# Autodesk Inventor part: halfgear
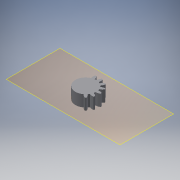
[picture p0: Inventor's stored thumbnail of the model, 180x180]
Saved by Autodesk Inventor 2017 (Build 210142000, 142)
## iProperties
Created: 2017-05
Part Number: halfgear
Material: Generic
Document SubType Name: Modeling
Designer: 1717440
Density: 1 g/cm^3
Appearance: Default
Author: 1717440
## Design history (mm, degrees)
workplane "Work Plane1"
sketch "Sketch1"
  geometry: L1 (-62.321, -3.687)-(-62.321, 3.767) reference; L2 (-22.321, -8.598)-(2.723, -8.598) reference; L3 (2.723, 8.678)-(-22.321, 8.678) reference; L4 (-0.521, 6.54)-(2.723, 6.54) reference; L5 (2.723, -6.46)-(1.723, -4.728) reference; L6 (1.723, -4.728)-(1.123, -4.728) reference; L7 (1.123, -4.728)-(0.123, -6.46) reference; L8 (0.123, -6.46)-(-0.477, -6.46) reference; L9 (-0.977, -5.594)-(-0.477, -6.46) reference; L10 (-2.577, -5.594)-(-0.977, -5.594) reference; L11 (-3.077, -6.46)-(-2.577, -5.594) reference; L12 (-3.077, -6.46)-(-3.677, -6.46) reference; L13 (-4.677, -4.728)-(-3.677, -6.46) reference; L14 (-5.277, -4.728)-(-4.677, -4.728) reference; L15 (-6.277, -6.46)-(-5.277, -4.728) reference; L16 (-6.277, -6.46)-(-6.877, -6.46) reference; L17 (-7.877, -4.728)-(-6.877, -6.46) reference; L18 (-8.477, -4.728)-(-7.877, -4.728) reference; L19 (-9.477, -6.46)-(-8.477, -4.728) reference; L20 (-9.477, -6.46)-(-10.077, -6.46) reference; L21 (-11.077, -4.728)-(-10.077, -6.46) reference; L22 (-11.677, -4.728)-(-11.077, -4.728) reference; L23 (-12.677, -6.46)-(-11.677, -4.728) reference; L24 (-12.677, -6.46)-(-13.277, -6.46) reference; L25 (-14.277, -4.728)-(-13.277, -6.46) reference; L26 (-14.877, -4.728)-(-14.277, -4.728) reference; L27 (-15.877, -6.46)-(-14.877, -4.728) reference; L28 (-15.877, -6.46)-(-16.477, -6.46) reference; L29 (-16.977, -5.594)-(-16.477, -6.46) reference; L30 (-18.577, -5.594)-(-16.977, -5.594) reference; L31 (-19.077, -6.46)-(-18.577, -5.594) reference; L32 (-19.077, -6.46)-(-22.321, -6.46) reference; L33 (-21.321, 4.808)-(-22.321, 6.54) reference; L34 (-20.721, 4.808)-(-21.321, 4.808) reference; L35 (-19.721, 6.54)-(-20.721, 4.808) reference; L36 (-19.721, 6.54)-(-19.121, 6.54) reference; L37 (-18.621, 5.674)-(-19.121, 6.54) reference; L38 (-17.021, 5.674)-(-18.621, 5.674) reference; L39 (-16.521, 6.54)-(-17.021, 5.674) reference; L40 (-16.521, 6.54)-(-15.921, 6.54) reference; L41 (-14.921, 4.808)-(-15.921, 6.54) reference; L42 (-14.321, 4.808)-(-14.921, 4.808) reference; L43 (-13.321, 6.54)-(-14.321, 4.808) reference; L44 (-13.321, 6.54)-(-12.721, 6.54) reference; L45 (-11.721, 4.808)-(-12.721, 6.54) reference; L46 (-11.121, 4.808)-(-11.721, 4.808) reference; L47 (-10.121, 6.54)-(-11.121, 4.808) reference; L48 (-10.121, 6.54)-(-9.521, 6.54) reference; L49 (-8.521, 4.808)-(-9.521, 6.54) reference; L50 (-7.921, 4.808)-(-8.521, 4.808) reference; L51 (-6.921, 6.54)-(-7.921, 4.808) reference; L52 (-6.921, 6.54)-(-6.321, 6.54) reference; L53 (-5.321, 4.808)-(-6.321, 6.54) reference; L54 (-4.721, 4.808)-(-5.321, 4.808) reference; L55 (-3.721, 6.54)-(-4.721, 4.808) reference; L56 (-3.721, 6.54)-(-3.121, 6.54) reference; L57 (0, 0)-(4.407, -4.407); L58 (0, 0)-(6.232, 0); L59 (4.407, -4.407)-(4.203, -4.61); L60 (4.203, -4.61)-(3.617, -4.336); L61 (3.048, -3.938)-(2.236, -3.127); L62 (3.938, -3.048)-(3.127, -2.236); L63 (4.61, -4.203)-(4.336, -3.617); L64 (4.407, -4.407)-(4.61, -4.203)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; C1 r 4.5 at (0, 0); C2 r 3.569 at (0, 0); C3 r 3.569 at (0, 0); C4 r 3.569 at (0, 0); C5 r 3.569 at (0, 0); C6 r 3.569 at (0, 0); C7 r 3.569 at (0, 0); C8 r 3.569 at (0, 0); A1 r 8.638 centre (-22.321, 0.04) between (-22.321, 8.678) and (-30.745, 1.951) reference; A2 r 8.638 centre (-22.321, 0.04) between (-30.745, -1.871) and (-22.321, -8.598) reference; A3 r 8.638 centre (2.723, 0.04) between (2.723, -8.598) and (2.723, 8.678) reference; A4 r 6.5 centre (2.723, 0.04) between (2.723, -6.46) and (2.723, 6.54) reference; A5 r 6.5 centre (-22.321, 0.04) between (-22.321, 6.54) and (-22.321, -6.46) reference; A6 r 2 centre (4.462, -2.524) between (3.048, -3.938) and (3.617, -4.336); A7 r 2 centre (2.524, -4.462) between (4.336, -3.617) and (3.938, -3.048); A8 r 2 centre (5.11, -0.402) between (4.426, -2.281) and (5.11, -2.402); A9 r 2 centre (4.173, -2.977) between (5.459, -1.445) and (4.857, -1.098); A10 r 2 centre (4.801, 1.796) between (4.976, -0.197) and (5.647, -0.017); A11 r 2 centre (5.04, -0.935) between (5.558, 0.997) and (4.866, 1.058); A12 r 2 centre (3.593, 3.657) between (4.593, 1.925) and (5.125, 2.371); A13 r 2 centre (4.963, 1.283) between (4.616, 3.253) and (3.963, 3.015); A14 r 2 centre (1.711, 4.832) between (3.349, 3.685) and (3.642, 4.315); A15 r 2 centre (3.956, 3.26) between (2.809, 4.899) and (2.318, 4.407); A16 r 2 centre (-0.492, 5.103) between (1.478, 4.755) and (1.478, 5.45); A17 r 2 centre (2.207, 4.627) between (0.475, 5.627) and (0.238, 4.974); A18 r 2 centre (-2.602, 4.417) between (-0.67, 4.934) and (-0.964, 5.564); A19 r 2 centre (0.045, 5.126) between (-1.947, 5.3) and (-1.887, 4.608); 10 further points
  constraints: 102 end point, 28 point on circle, 22 centre point, 14 point on line, 5 symmetric about line, 2 coincident, 2 tangent, 1 equal length, 1 horizontal, 1 parallel, 1 perpendicular, 140 other
  dimensions: "d0" = 9 diameter of C1; "d1" = 6.232 distance of L57.start L57.end; "d2" = 45 deg angle of L57 L58; "d3" = 0.2875 distance of L57.end L59.end; "d4" = 1 distance of L59.end point (3.297, -4.187); "d8" = 110 deg angle of L59 L60; "d9" = 2 radius of A6 (derived); "d12" = 150 deg dimension on L57.start A6.centre A18.centre
extrude "Extrusion1" new body sketch "Sketch1" distance "d14" = 5; taper "d15" = 0 deg
body "Solid1"
